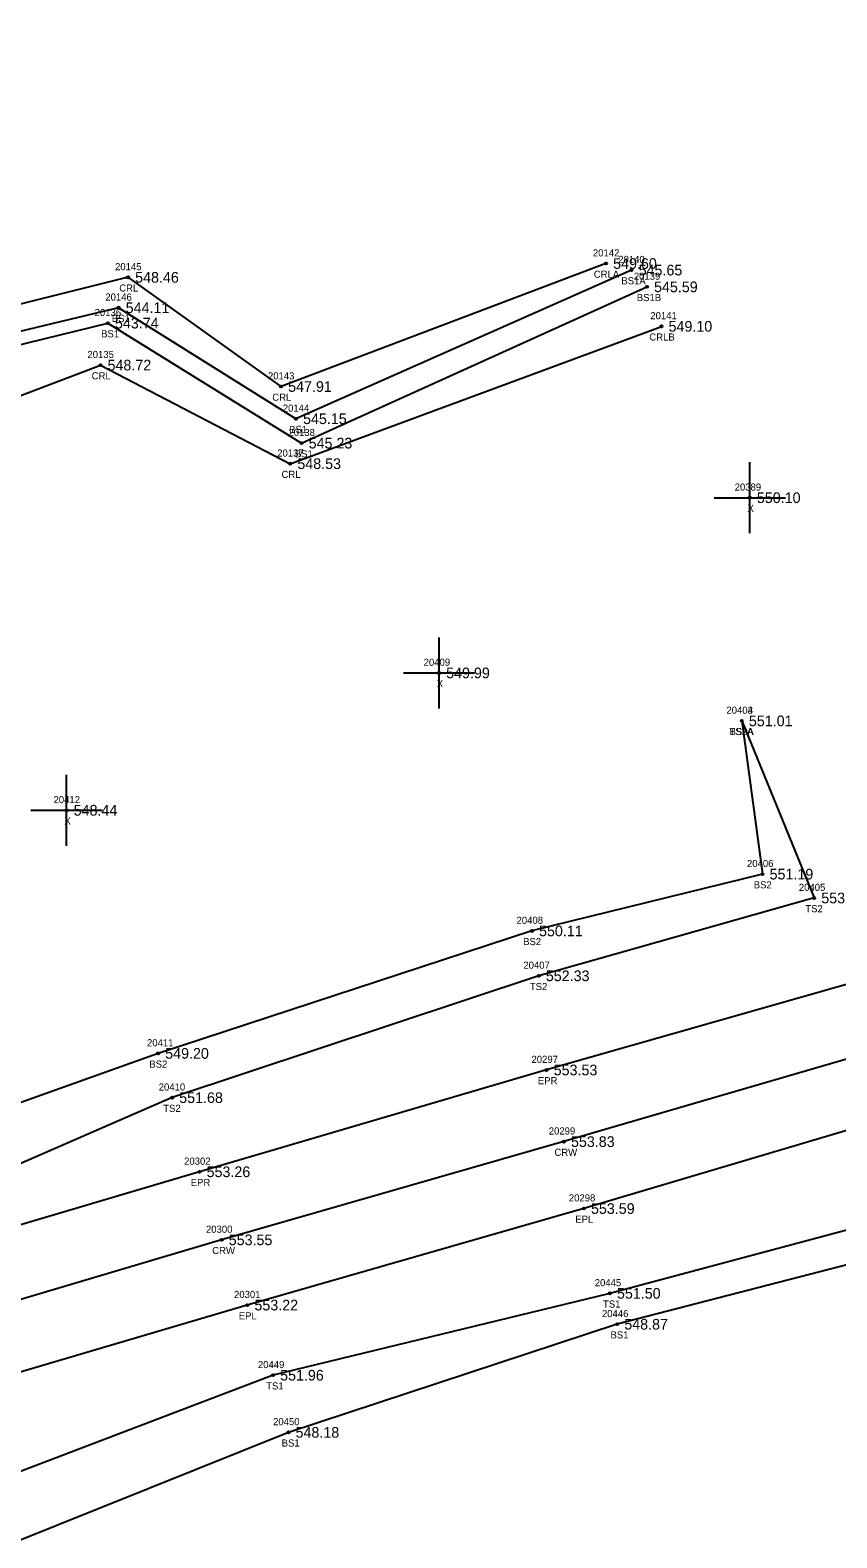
# Model space of a CAD drawing. Extents: x 1540443 to 1541844, y 887157 to 888162.
# Drawn here: x 1541264.6 to 1541377.9, y 887681.2 to 887893.1 of the extents above; entities that cross this region are included whole.
import ezdxf

# ---------------------------------------------------------------- set-up
doc = ezdxf.new("R2010")
doc.units = 0
for name, color, linetype in [('RD_DTM_BkLn1', 7, 'Continuous'), ('RD_DTM_BkLn2', 7, 'Continuous'), ('RD_DTM_BkLn_txCode', 7, 'Continuous'), ('RD_EX_H2O', 7, 'Continuous'), ('RD_EX_H2O_txCode', 7, 'Continuous'), ('RD_EX_Misc', 7, 'Continuous'), ('RD_EX_Misc_txCode', 7, 'Continuous'), ('RD_EX_Road', 7, 'Continuous'), ('RD_EX_Road_txCode', 7, 'Continuous'), ('RD_EX_TX_H2O_ELEV', 7, 'Continuous'), ('RD_EX_TX_Misc_ELEV', 7, 'Continuous'), ('RD_EX_TX_Road_ELEV', 7, 'Continuous'), ('RD_HC_Survey_ELEV', 7, 'Continuous'), ('RD_HC_Survey_txCode', 7, 'Continuous'), ('RD_SMD_Locator', 7, 'Continuous')]:
    doc.layers.add(name, color=color, linetype=linetype)

msp = doc.modelspace()

# ---------------------------------------------------------------- linework, layer by layer
at = {"layer": 'RD_DTM_BkLn1'}
msp.add_lwpolyline([(1541819.64, 887879.04), (1541771.84, 887865.01), (1541723.55, 887850.95), (1541675.82, 887836.26), (1541627.89, 887822.08), (1541580.01, 887807.87), (1541531.93, 887793.38), (1541484.13, 887778.91), (1541435.66, 887765.21), (1541388.1, 887751.04), (1541339.55, 887736.89), (1541291.46, 887723.08), (1541243.5, 887708.82), (1541195.27, 887694.78), (1541169.43, 887686.85)], dxfattribs=at)
at = {"layer": 'RD_DTM_BkLn2'}
for points in [[(1541349.06, 887859.41), (1541301.9, 887838.51), (1541276.98, 887854.12), (1541250.17, 887847.68), (1541235.42, 887838.4), (1541226.46, 887818.66), (1541206.99, 887816.69), (1541177.91, 887783.05), (1541174.61, 887756.9), (1541155.39, 887744.58), (1541154.65, 887729.69), (1541126.74, 887754.56), (1541108.32, 887769.11), (1541148.46, 887831.42), (1541178.11, 887856.6), (1541159.66, 887905.22), (1541133.37, 887953.98), (1541101.85, 887998.23), (1541093.93, 888039.66), (1541072.92, 888058.86), (1541087, 888085), (1541104.04, 888122.31), (1541088.02, 888158.63)], [(1541824.97, 887864.95), (1541773.24, 887848.9), (1541728.33, 887834.59), (1541680.22, 887820.65), (1541632.2, 887806.6), (1541586.15, 887794.2), (1541535.56, 887777.78), (1541490.03, 887763.87), (1541442.11, 887749.28), (1541414.74, 887732.66), (1541394.55, 887728.51), (1541346.01, 887715.56), (1541298.68, 887704.05), (1541256.52, 887687.99), (1541253.67, 887682.12), (1541204.18, 887671.81), (1541185.24, 887668.7), (1541173.43, 887674.53)], [(1541826.01, 887862.16), (1541773.99, 887846.34), (1541729.05, 887832.97), (1541681.03, 887818.46), (1541632.94, 887804.51), (1541587.44, 887789.41), (1541536.78, 887773.27), (1541491.06, 887758.08), (1541445.99, 887740.14), (1541416.24, 887728.45), (1541395.49, 887723.75), (1541347.04, 887711.22), (1541300.85, 887696.02), (1541261.64, 887680.26), (1541255.59, 887675.42), (1541206.42, 887663.07), (1541174, 887652.79)], [(1541154.57, 887667.56), (1541150.51, 887698.19), (1541151.23, 887717.23), (1541159.67, 887729.57), (1541158.46, 887743.28), (1541175.94, 887756.06), (1541180.1, 887781.42), (1541208.84, 887815.45), (1541228.8, 887816.99), (1541237.09, 887835.99), (1541252.66, 887846.36), (1541275.47, 887851.95), (1541302.69, 887835.08), (1541351.22, 887857.05)], [(1541364.55, 887796.04), (1541367.46, 887774.49), (1541335.06, 887766.51), (1541282.53, 887749.29), (1541236.45, 887732.84), (1541182.66, 887719.43), (1541167.69, 887723.41), (1541159.31, 887712.61)], [(1541364.55, 887796.04), (1541374.72, 887771.14), (1541336.02, 887760.2), (1541284.5, 887743.07), (1541239.22, 887723.36), (1541191.26, 887711.45), (1541166.05, 887698.62)]]:
    msp.add_lwpolyline(points, dxfattribs=at)
at = {"layer": 'RD_EX_H2O'}
for points in [[(1541345.47, 887860.33), (1541299.81, 887843.04), (1541278.31, 887858.39), (1541248.14, 887850.88), (1541232.97, 887840.42), (1541206.44, 887819.7), (1541175.27, 887783.56), (1541168.89, 887762.72), (1541151.82, 887746.65), (1541151.42, 887737.55), (1541129.57, 887759.43), (1541125.03, 887781.17), (1541150.06, 887828.48), (1541182.67, 887854.92), (1541164.01, 887910.29), (1541139.24, 887954.07), (1541111.52, 888003.47), (1541100.67, 888047.04), (1541091.5, 888080.23), (1541107.64, 888120.67), (1541095.14, 888160.09)], [(1541162.66, 887669.25), (1541156.85, 887699.34), (1541155.63, 887713.65), (1541161.97, 887728.63), (1541167.93, 887745.6), (1541178.82, 887753.04), (1541184.89, 887779.89), (1541211.43, 887808.11), (1541231.17, 887813.83), (1541242.51, 887826.96), (1541257.39, 887839.59), (1541274.43, 887846.05), (1541301.1, 887832.19), (1541353.26, 887851.5)]]:
    msp.add_lwpolyline(points, dxfattribs=at)
at = {"layer": 'RD_EX_Misc'}
for p, q in [((1541365.67, 887822.41), (1541365.67, 887832.41)), ((1541360.67, 887827.41), (1541370.67, 887827.41)), ((1541322.01, 887797.78), (1541322.01, 887807.78)), ((1541317.01, 887802.78), (1541327.01, 887802.78)), ((1541269.67, 887778.47), (1541269.67, 887788.47)), ((1541264.67, 887783.47), (1541274.67, 887783.47))]:
    msp.add_line(p, q, dxfattribs=at)
at = {"layer": 'RD_EX_Road'}
for points in [[(1541816.45, 887889.18), (1541769.26, 887875.17), (1541720.7, 887860.02), (1541673.15, 887846.35), (1541624.52, 887832.03), (1541577.1, 887817.68), (1541529.45, 887803.59), (1541481.09, 887788.89), (1541433.23, 887775.3), (1541384.84, 887760.56), (1541337.12, 887746.96), (1541288.35, 887732.65), (1541241.37, 887718.72), (1541192.23, 887703.89), (1541166.88, 887695.38)], [(1541823.08, 887870.08), (1541774.23, 887855.6), (1541726.64, 887841.16), (1541678.89, 887827.09), (1541630.15, 887812.57), (1541582.93, 887798.43), (1541534.59, 887784.1), (1541487.04, 887769.99), (1541438.64, 887755.66), (1541391.44, 887742.05), (1541342.36, 887727.48), (1541295.07, 887713.91), (1541246.74, 887699.66), (1541197.81, 887684.79), (1541172.48, 887676.63)]]:
    msp.add_lwpolyline(points, dxfattribs=at)
at = {"layer": 'RD_SMD_Locator'}
for centre in [(1541345.47, 887860.33), (1541349.06, 887859.41), (1541278.31, 887858.39), (1541351.22, 887857.05), (1541276.98, 887854.12), (1541275.47, 887851.95), (1541353.26, 887851.5), (1541274.43, 887846.05), (1541299.81, 887843.04), (1541301.9, 887838.51), (1541302.69, 887835.08), (1541301.1, 887832.19), (1541365.67, 887827.41), (1541322.01, 887802.78), (1541364.55, 887796.04), (1541364.55, 887796.04), (1541269.67, 887783.47), (1541367.46, 887774.49), (1541374.72, 887771.14), (1541335.06, 887766.51), (1541336.02, 887760.2), (1541282.53, 887749.29), (1541337.12, 887746.96), (1541284.5, 887743.07), (1541339.55, 887736.89), (1541288.35, 887732.65), (1541342.36, 887727.48), (1541291.46, 887723.08), (1541346.01, 887715.56), (1541295.07, 887713.91), (1541347.04, 887711.22), (1541298.68, 887704.05), (1541300.85, 887696.02)]:
    msp.add_circle(centre, 0.15, dxfattribs=at)

# ---------------------------------------------------------------- texts
at = {"layer": 'RD_DTM_BkLn_txCode'}
for s, p in [('20140', (1541347.19, 887860.41)), ('BS1A', (1541347.63, 887857.41)), ('20139', (1541349.38, 887858.05)), ('20146', (1541275.12, 887855.12)), ('BS1B', (1541349.8, 887855.05)), ('20136', (1541273.61, 887852.95)), ('BS1', (1541276.03, 887852.12)), ('BS1', (1541274.53, 887849.95)), ('20144', (1541300.06, 887839.51)), ('20138', (1541300.85, 887836.08)), ('BS1', (1541300.95, 887836.51)), ('BS1', (1541301.74, 887833.08)), ('20403', (1541362.39, 887797.04)), ('20404', (1541362.39, 887797.04)), ('TS2A', (1541362.82, 887794.04)), ('BS2A', (1541362.83, 887794.04)), ('20406', (1541365.28, 887775.49)), ('BS2', (1541366.23, 887772.49)), ('20405', (1541372.57, 887772.14)), ('TS2', (1541373.48, 887769.14)), ('20408', (1541332.9, 887767.51)), ('BS2', (1541333.83, 887764.51)), ('20407', (1541333.86, 887761.2)), ('TS2', (1541334.77, 887758.2)), ('20411', (1541280.97, 887750.29)), ('BS2', (1541281.3, 887747.29)), ('20410', (1541282.62, 887744.07)), ('TS2', (1541283.25, 887741.07)), ('20445', (1541343.89, 887716.56)), ('20446', (1541344.9, 887712.22)), ('TS1', (1541345.05, 887713.56)), ('BS1', (1541346.1, 887709.22)), ('20449', (1541296.56, 887705.05)), ('TS1', (1541297.72, 887702.05)), ('20450', (1541298.69, 887697.02)), ('BS1', (1541299.9, 887694.02))]:
    msp.add_text(s, height=1, dxfattribs=at).set_placement(p)
at = {"layer": 'RD_EX_H2O_txCode'}
for s, p in [('20142', (1541343.63, 887861.33)), ('20145', (1541276.48, 887859.39)), ('CRLA', (1541343.75, 887858.33)), ('CRL', (1541277.08, 887856.39)), ('20141', (1541351.7, 887852.5)), ('CRLB', (1541351.56, 887849.5)), ('20135', (1541272.6, 887847.05)), ('CRL', (1541273.2, 887844.05)), ('20143', (1541297.97, 887844.04)), ('CRL', (1541298.58, 887841.04)), ('20137', (1541299.27, 887833.19)), ('CRL', (1541299.87, 887830.19))]:
    msp.add_text(s, height=1, dxfattribs=at).set_placement(p)
at = {"layer": 'RD_EX_Misc_txCode'}
for s, p in [('20389', (1541363.55, 887828.41)), ('X', (1541365.36, 887825.41)), ('20409', (1541319.85, 887803.78)), ('X', (1541321.69, 887800.78)), ('20412', (1541267.84, 887784.47)), ('X', (1541269.36, 887781.47))]:
    msp.add_text(s, height=1, dxfattribs=at).set_placement(p)
at = {"layer": 'RD_EX_Road_txCode'}
for s, p in [('20297', (1541335, 887747.96)), ('EPR', (1541335.89, 887744.96)), ('20302', (1541286.19, 887733.65)), ('EPR', (1541287.12, 887730.65)), ('20298', (1541340.25, 887728.48)), ('EPL', (1541341.16, 887725.48)), ('20301', (1541293.2, 887714.91)), ('EPL', (1541293.87, 887711.91))]:
    msp.add_text(s, height=1, dxfattribs=at).set_placement(p)
at = {"layer": 'RD_EX_TX_H2O_ELEV'}
for s, p in [('548.46', (1541279.31, 887857.64)), ('549.60', (1541346.47, 887859.58)), ('549.10', (1541354.26, 887850.75)), ('548.72', (1541275.43, 887845.3)), ('547.91', (1541300.81, 887842.29)), ('548.53', (1541302.1, 887831.44))]:
    msp.add_text(s, height=1.5, dxfattribs=at).set_placement(p)
at = {"layer": 'RD_EX_TX_Misc_ELEV'}
for s, p in [('545.65', (1541350.06, 887858.66)), ('545.59', (1541352.22, 887856.3)), ('544.11', (1541277.98, 887853.37)), ('543.74', (1541276.47, 887851.2)), ('545.15', (1541302.9, 887837.76)), ('545.23', (1541303.69, 887834.33)), ('550.10', (1541366.67, 887826.66)), ('549.99', (1541323.01, 887802.03)), ('551.01', (1541365.55, 887795.29)), ('551.01', (1541365.55, 887795.29)), ('548.44', (1541270.67, 887782.72)), ('551.19', (1541368.46, 887773.74)), ('553.10', (1541375.72, 887770.39)), ('550.11', (1541336.06, 887765.76)), ('552.33', (1541337.02, 887759.45)), ('549.20', (1541283.53, 887748.54)), ('551.68', (1541285.5, 887742.32)), ('551.50', (1541347.01, 887714.81)), ('548.87', (1541348.04, 887710.47)), ('551.96', (1541299.68, 887703.3)), ('548.18', (1541301.85, 887695.27))]:
    msp.add_text(s, height=1.5, dxfattribs=at).set_placement(p)
at = {"layer": 'RD_EX_TX_Road_ELEV'}
for s, p in [('553.53', (1541338.12, 887746.21)), ('553.26', (1541289.35, 887731.9)), ('553.59', (1541343.36, 887726.73)), ('553.22', (1541296.07, 887713.16))]:
    msp.add_text(s, height=1.5, dxfattribs=at).set_placement(p)
at = {"layer": 'RD_HC_Survey_ELEV'}
for s, p in [('553.83', (1541340.55, 887736.14)), ('553.55', (1541292.46, 887722.33))]:
    msp.add_text(s, height=1.5, dxfattribs=at).set_placement(p)
at = {"layer": 'RD_HC_Survey_txCode'}
for s, p in [('20299', (1541337.43, 887737.89)), ('CRW', (1541338.23, 887734.89)), ('20300', (1541289.26, 887724.08)), ('CRW', (1541290.14, 887721.08))]:
    msp.add_text(s, height=1, dxfattribs=at).set_placement(p)

doc.saveas('drawing.dxf')
